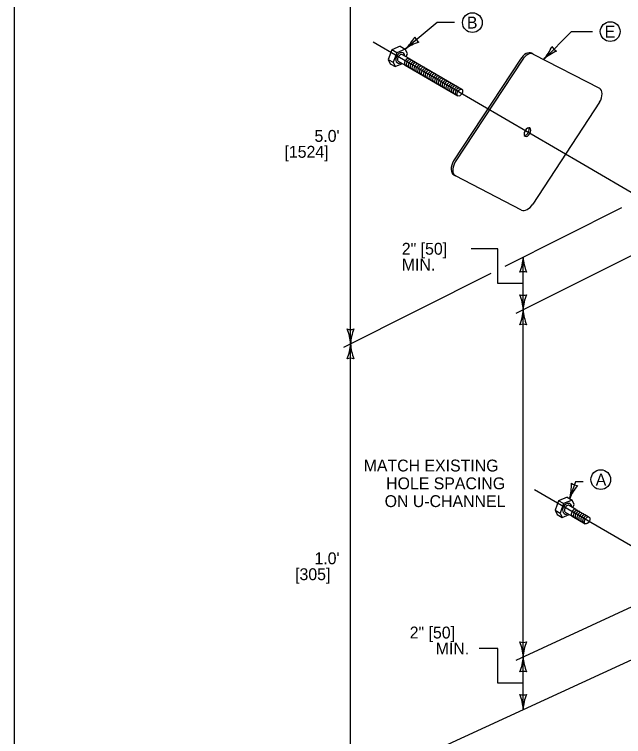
# Model space of a CAD drawing. Extents: x 49991.4 to 50021, y 49987.6 to 50011.4.
# Drawn here: x 49999.384 to 50002.465, y 49991.676 to 49995.327 of the extents above; entities that cross this region are included whole.
import ezdxf

# ---------------------------------------------------------------- set-up
doc = ezdxf.new("R2010")
doc.units = 0
for name, color, linetype in [('Level 1', 7, 'Continuous'), ('Level 2', 7, 'Continuous'), ('Level 3', 7, 'Continuous'), ('Level 5', 7, 'Continuous')]:
    doc.layers.add(name, color=color, linetype=linetype)

msp = doc.modelspace()

# ---------------------------------------------------------------- linework, layer by layer
at = {"layer": 'Level 1'}
for p, q in [((50001.3355, 49995.1659), (50001.2925, 49995.148)), ((50001.3355, 49995.1659), (50001.3608, 49995.1512)), ((50001.2925, 49995.148), (50001.2742, 49995.0998)), ((50001.3178, 49995.1332), (50001.2925, 49995.148)), ((50001.3178, 49995.1332), (50001.2995, 49995.085)), ((50001.3608, 49995.1512), (50001.3178, 49995.1332)), ((50001.38, 49995.1039), (50001.3466, 49995.1234)), ((50001.3713, 49995.1293), (50001.3608, 49995.1512)), ((50001.365, 49995.1126), (50001.3713, 49995.1293)), ((50002.0084, 49995.1263), (50002.0001, 49995.1312)), ((50002.0084, 49995.1263), (50002.3432, 49994.9533)), ((50001.2742, 49995.0998), (50001.2847, 49995.0779)), ((50001.2742, 49995.0998), (50001.2995, 49995.085)), ((50001.2995, 49995.085), (50001.31, 49995.0632)), ((50001.31, 49995.0632), (50001.3459, 49995.0782)), ((50001.3255, 49995.09), (50001.3603, 49995.0698)), ((50001.38, 49995.1039), (50001.6465, 49994.9485)), ((50001.9433, 49995.1008), (50001.6054, 49994.5862)), ((50001.9517, 49995.0959), (50001.6137, 49994.5813)), ((50001.2847, 49995.0779), (50001.31, 49995.0632)), ((50001.3603, 49995.0698), (50001.6269, 49994.9146)), ((50002.344, 49994.8828), (50002.0061, 49994.3682)), ((50001.6146, 49994.5107), (50001.6062, 49994.5156)), ((50001.9493, 49994.3378), (50001.6146, 49994.5107)), ((50002.1366, 49992.8685), (50002.1183, 49992.8204)), ((50002.1796, 49992.8865), (50002.1366, 49992.8685)), ((50002.162, 49992.8537), (50002.1366, 49992.8685)), ((50002.162, 49992.8537), (50002.1437, 49992.8056)), ((50002.205, 49992.8717), (50002.162, 49992.8537)), ((50002.1796, 49992.8865), (50002.205, 49992.8717)), ((50002.2155, 49992.8498), (50002.205, 49992.8717)), ((50002.1183, 49992.8204), (50002.1288, 49992.7985)), ((50002.1183, 49992.8204), (50002.1437, 49992.8056)), ((50002.2241, 49992.8245), (50002.1905, 49992.8437)), ((50002.2092, 49992.8332), (50002.2155, 49992.8498)), ((50002.2241, 49992.8246), (50002.2907, 49992.7857)), ((50002.1288, 49992.7985), (50002.1542, 49992.7837)), ((50002.1437, 49992.8056), (50002.1542, 49992.7837)), ((50002.1542, 49992.7837), (50002.1901, 49992.7987)), ((50002.1698, 49992.8108), (50002.2044, 49992.7904)), ((50002.2046, 49992.7906), (50002.2712, 49992.7517))]:
    msp.add_line(p, q, dxfattribs=at)
msp.add_lwpolyline([(49999.3835, 49998.9992), (50016.7501, 49998.9992), (50016.7501, 49987.7988), (49999.3835, 49987.7988)], close=True, dxfattribs=at)
for centre, major_axis, ratio, start_param, end_param in [((50001.3354, 49995.1072), (0.0145, 0.0251), 0.715069, 5.453325, 10.242041), ((50001.3354, 49995.1072), (0.0098, 0.0169), 0.57735, 6.151544, 9.424778), ((50001.9706, 49995.0781), (0.0304, 0.0526), 0.57735, 0.026952, 1.471473), ((50001.9789, 49995.0733), (0.0304, 0.0526), 0.57735, 0.026952, 1.471473), ((50001.3702, 49995.0869), (0.0098, 0.0169), 0.57735, 0.000016, 3.141596), ((50001.3797, 49995.0814), (0.0098, 0.0169), 0.57735, 0.000016, 3.141596), ((50001.3892, 49995.0758), (0.0098, 0.0169), 0.57735, 0.000016, 3.141596), ((50001.3987, 49995.0703), (0.0098, 0.0169), 0.57735, 0.000016, 3.141596), ((50001.4082, 49995.0647), (0.0098, 0.0169), 0.57735, 0.000016, 3.141596), ((50001.4178, 49995.0592), (0.0098, 0.0169), 0.57735, 0.000016, 3.141596), ((50001.4273, 49995.0536), (0.0098, 0.0169), 0.57735, 0.000016, 3.141596), ((50001.4368, 49995.0481), (0.0098, 0.0169), 0.57735, 0.000016, 3.141596), ((50001.4463, 49995.0425), (0.0098, 0.0169), 0.57735, 0.000016, 3.141596), ((50001.4558, 49995.037), (0.0098, 0.0169), 0.57735, 0.000016, 3.141596), ((50001.4654, 49995.0314), (0.0098, 0.0169), 0.57735, 0.000016, 3.141596), ((50001.4749, 49995.0259), (0.0098, 0.0169), 0.57735, 0.000016, 3.141596), ((50001.4844, 49995.0203), (0.0098, 0.0169), 0.57735, 0.000016, 3.141596), ((50001.4939, 49995.0148), (0.0098, 0.0169), 0.57735, 0.000016, 3.141596), ((50001.5034, 49995.0092), (0.0098, 0.0169), 0.57735, 0.000016, 3.141596), ((50001.513, 49995.0037), (0.0098, 0.0169), 0.57735, 0.000016, 3.141596), ((50001.5225, 49994.9981), (0.0098, 0.0169), 0.57735, 0.000016, 3.141596), ((50001.532, 49994.9926), (0.0098, 0.0169), 0.57735, 0.000016, 3.141596), ((50001.5415, 49994.987), (0.0098, 0.0169), 0.57735, 0.000016, 3.141596), ((50001.551, 49994.9815), (0.0098, 0.0169), 0.57735, 0.000016, 3.141596), ((50001.5605, 49994.976), (0.0098, 0.0169), 0.57735, 0.000016, 3.141596), ((50001.5701, 49994.9704), (0.0098, 0.0169), 0.57735, 0.000016, 3.141596), ((50001.5796, 49994.9648), (0.0098, 0.0169), 0.57735, 0.000016, 3.141596), ((50001.5891, 49994.9593), (0.0098, 0.0169), 0.57735, 0.000016, 3.141596), ((50001.5986, 49994.9537), (0.0098, 0.0169), 0.57735, 0.000016, 3.141596), ((50001.6081, 49994.9482), (0.0098, 0.0169), 0.57735, 0.000016, 3.141596), ((50001.6177, 49994.9426), (0.0098, 0.0169), 0.57735, 0.000016, 3.141596), ((50001.6272, 49994.9371), (0.0098, 0.0169), 0.57735, 0.000016, 3.141596), ((50002.3137, 49994.9003), (0.0304, 0.0526), 0.57735, 4.71239, 6.310148), ((50001.9789, 49994.732), (0.0122, 0.0212), 0.57735, 3.153573, 9.424778), ((50001.9706, 49994.7369), (0.0122, 0.0212), 0.57735, 3.487866, 5.932002), ((50001.6358, 49994.5687), (0.0304, 0.0526), 0.57735, 1.570791, 3.168563), ((50001.6441, 49994.5638), (0.0304, 0.0526), 0.57735, 1.570791, 3.168563), ((50001.9789, 49994.3908), (0.0304, 0.0526), 0.57735, 3.168548, 4.613061), ((50002.1796, 49992.8277), (0.0145, 0.0251), 0.715069, 5.453325, 10.242041), ((50002.1796, 49992.8277), (0.0098, 0.0169), 0.57735, 6.151544, 9.424778), ((50002.2143, 49992.8075), (0.0098, 0.0169), 0.57735, 0.000016, 3.141596), ((50002.2238, 49992.8019), (0.0098, 0.0169), 0.57735, 0.000016, 3.141596), ((50002.2333, 49992.7964), (0.0098, 0.0169), 0.57735, 0.000016, 3.141596), ((50002.2429, 49992.7908), (0.0098, 0.0169), 0.57735, 0.000016, 3.141596), ((50002.2524, 49992.7853), (0.0098, 0.0169), 0.57735, 0.000016, 3.141596), ((50002.2619, 49992.7797), (0.0098, 0.0169), 0.57735, 0.000016, 3.141596), ((50002.2714, 49992.7742), (0.0098, 0.0169), 0.57735, 0.000016, 3.141596)]:
    msp.add_ellipse(centre, major_axis=major_axis, ratio=ratio, start_param=start_param, end_param=end_param, dxfattribs=at)
for centre in [(50001.6367, 49994.9315), (50002.2809, 49992.7686)]:
    msp.add_ellipse(centre, major_axis=(0.0098, 0.0169), ratio=0.57735, dxfattribs=at)
at = {"layer": 'Level 2'}
for centre in [(50001.7003, 49995.2856), (50002.3975, 49995.2401), (50002.3498, 49992.9749)]:
    msp.add_circle(centre, 0.05, dxfattribs=at)
at = {"layer": 'Level 3'}
for p, q in [((50001.084, 49993.6606), (50001.084, 49995.6093)), ((50001.8654, 49994.0533), (50002.4562, 49994.3502)), ((50001.9215, 49993.8157), (50002.7704, 49994.2423)), ((50001.9572, 49993.8337), (50001.9572, 49994.0995)), ((50001.7939, 49994.0174), (50001.0489, 49993.6429)), ((50001.9572, 49992.0786), (50001.9572, 49993.8337)), ((50001.0836, 49991.4116), (50001.084, 49993.6622)), ((50001.921, 49992.062), (50002.7604, 49992.4511)), ((50001.0472, 49991.3949), (50002.7101, 49992.1589)), ((50001.9572, 49991.813), (50001.9572, 49992.0788))]:
    msp.add_line(p, q, dxfattribs=at)
for points in [[(50001.6103, 49995.2856), (50001.5218, 49995.2856), (50001.3608, 49995.1512)], [(50002.0609, 49995.0992), (50002.2022, 49995.2405), (50002.3075, 49995.2402)], [(50001.9572, 49993.9666), (50001.8297, 49993.9666), (50001.8297, 49994.142), (50001.6943, 49994.142)], [(50002.261, 49992.9643), (50002.2215, 49992.9643), (50002.1923, 49992.8791)], [(50001.9572, 49991.9459), (50001.8297, 49991.9459), (50001.8297, 49992.1213), (50001.7343, 49992.1213)]]:
    msp.add_lwpolyline(points, dxfattribs=at)
for centre, radius, start, end in [((50001.2028, 49995.3224), 0.233, 312.699, 331.9489), ((50001.4593, 49995.2334), 0.0548, 202.0105, 237.7329), ((50001.4962, 49994.9748), 0.2223, 107.3277, 127.5112), ((50001.8882, 49995.2556), 0.233, 317.8276, 337.0775), ((50002.1515, 49995.1899), 0.0548, 207.1391, 242.8615), ((50002.2115, 49994.9357), 0.2223, 112.4563, 132.6398), ((50001.7351, 49994.1086), 0.2223, 337.456, 357.6395), ((50002.19, 49994.111), 0.233, 182.8273, 202.0772), ((50001.9572, 49993.9712), 0.0548, 72.1388, 107.8612), ((50001.9572, 49993.9619), 0.0548, 252.1388, 287.8612), ((50001.7245, 49993.8222), 0.233, 2.8273, 22.0772), ((50001.9572, 49993.9619), 0.0548, 252.1388, 287.8612), ((50001.7245, 49993.8222), 0.233, 2.8273, 22.0772), ((50002.1794, 49993.8245), 0.2223, 157.456, 177.6395), ((50002.1794, 49993.8245), 0.2223, 157.456, 177.6395), ((50001.7351, 49993.8428), 0.2223, 337.456, 357.6395), ((50002.19, 49993.8451), 0.233, 182.8273, 202.0772), ((50001.084, 49993.7888), 0.0548, 252.1388, 287.8612), ((50000.8513, 49993.6491), 0.233, 2.8273, 22.0772), ((50001.3061, 49993.6514), 0.2223, 157.456, 177.6395), ((50001.9572, 49993.7054), 0.0548, 72.1388, 107.8612), ((50000.8619, 49993.6714), 0.2223, 337.4458, 357.6293), ((50001.3167, 49993.6736), 0.233, 182.8171, 202.067), ((50001.084, 49993.534), 0.0548, 72.1286, 107.851), ((50001.9684, 49992.9436), 0.233, 343.9386, 3.1885), ((50002.3995, 49992.7985), 0.2223, 138.5673, 158.7508), ((50002.2338, 49993.0004), 0.0548, 233.2501, 268.9725), ((50001.9573, 49992.2068), 0.0548, 252.1388, 287.8612), ((50001.7245, 49992.0671), 0.233, 2.8273, 22.0772), ((50002.1794, 49992.0695), 0.2223, 157.456, 177.6395), ((50001.7351, 49992.088), 0.2223, 337.456, 357.6395), ((50002.19, 49992.0903), 0.233, 182.8273, 202.0772), ((50001.9572, 49991.9506), 0.0548, 72.1388, 107.8612), ((50001.9572, 49991.9412), 0.0548, 252.1388, 287.8612), ((50001.7245, 49991.8015), 0.233, 2.8273, 22.0772), ((50001.9572, 49991.9412), 0.0548, 252.1388, 287.8612), ((50001.7245, 49991.8015), 0.233, 2.8273, 22.0772), ((50002.1794, 49991.8038), 0.2223, 157.456, 177.6395), ((50002.1794, 49991.8038), 0.2223, 157.456, 177.6395)]:
    msp.add_arc(centre, radius, start, end, dxfattribs=at)
at = {"layer": 'Level 5'}
for p, q in [((50002.2637, 49994.566), (50001.1987, 49995.1868)), ((50004.1511, 49993.4657), (50002.2637, 49994.566)), ((50003.6421, 49991.9751), (50002.0146, 49992.9239))]:
    msp.add_line(p, q, dxfattribs=at)

# ---------------------------------------------------------------- texts
at = {"layer": 'Level 2'}
for s, p in [('B', (50001.6725, 49995.2556)), ('E', (50002.3695, 49995.2101)), ("5.0'", (50000.9015, 49994.6827)), ('[1524]', (50000.7497, 49994.6023)), ('2" [50]', (50001.3432, 49994.1121)), ('MIN.', (50001.3432, 49994.0317)), ('MATCH EXISTING ', (50001.1504, 49993.0161)), ('A', (50002.3241, 49992.9449)), ('HOLE SPACING ', (50001.2639, 49992.9261)), ('ON U-CHANNEL', (50001.2565, 49992.8361)), ("1.0'", (50000.9013, 49992.5471)), ('[305]', (50000.8034, 49992.4667)), ('2" [50]', (50001.3832, 49992.1718)), ('MIN.', (50001.5146, 49992.0914))]:
    msp.add_text(s, height=0.06, dxfattribs=at).set_placement(p)

doc.saveas('drawing.dxf')
